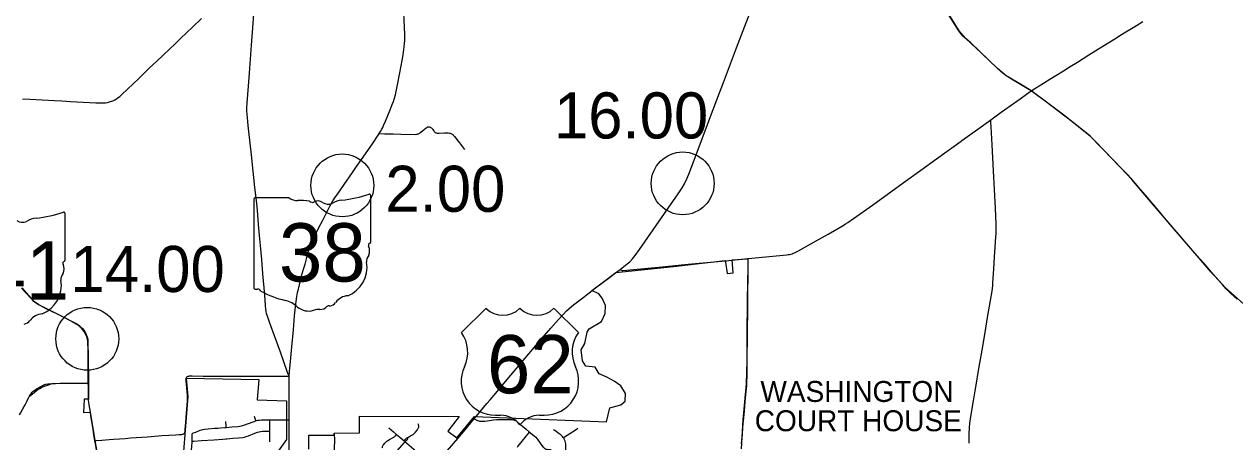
# Model space of a CAD drawing. Extents: x 1597222 to 1925846, y 496284 to 911751.
# Drawn here: x 1698562 to 1727439, y 566794 to 576766 of the extents above; entities that cross this region are included whole.
import ezdxf

# ---------------------------------------------------------------- set-up
doc = ezdxf.new("R2010")
doc.units = 0
for name, color, linetype in [('Default', 7, 'Continuous'), ('GM_X_City_Street', 7, 'Continuous'), ('GM_X_Corporation', 7, 'Continuous'), ('GM_X_Corporation_Text', 7, 'Continuous'), ('GM_X_County_Road', 7, 'Continuous'), ('GM_X_State_Route', 7, 'Continuous'), ('GM_X_State_Shield', 7, 'Continuous'), ('GM_X_Township', 7, 'Continuous'), ('GM_X_Township_Road', 7, 'Continuous'), ('GM_X_US_Route', 7, 'Continuous'), ('GM_X_US_Shield', 7, 'Continuous')]:
    doc.layers.add(name, color=color, linetype=linetype)

msp = doc.modelspace()

# ---------------------------------------------------------------- linework, layer by layer
at = {"layer": 'Default'}
for centre in [(1706150, 572917), (1706150, 572917), (1714269, 572965), (1714269, 572965), (1700066, 569254), (1700066, 569254)]:
    msp.add_circle(centre, 750, dxfattribs=at)
at = {"layer": 'GM_X_City_Street'}
for points in [[(1698690, 567886), (1698759, 567939), (1698809, 567983), (1698848, 568013), (1698889, 568042), (1698931, 568068), (1698975, 568091), (1699021, 568111), (1699067, 568129), (1699115, 568144), (1699227, 568183)], [(1698690, 567886), (1698719, 567934), (1698734, 567956), (1698754, 567978), (1698779, 568000), (1698817, 568031), (1698858, 568059), (1698899, 568086), (1698943, 568110), (1698987, 568132), (1699033, 568151), (1699079, 568167), (1699126, 568176), (1699175, 568182), (1699227, 568183)], [(1699227, 568183), (1699259, 568186), (1699309, 568187), (1699422, 568191), (1699683, 568193), (1699976, 568196), (1700091, 568197)], [(1698451, 567435), (1698474, 567479), (1698532, 567579), (1698587, 567680), (1698623, 567754), (1698665, 567843), (1698681, 567872), (1698690, 567886)], [(1703380, 567139), (1703378, 567172), (1703371, 567280)], [(1703380, 567139), (1703517, 567149), (1703658, 567161), (1703703, 567168), (1703745, 567177), (1703798, 567194), (1704023, 567274), (1704087, 567295)], [(1704087, 567295), (1704085, 567301), (1704056, 567401)], [(1704087, 567295), (1704101, 567300), (1704133, 567308), (1704175, 567314), (1704220, 567317), (1704352, 567318), (1704423, 567318)], [(1704422, 567046), (1704422, 567091), (1704423, 567274), (1704423, 567318)], [(1704423, 567318), (1704594, 567318), (1704830, 567315), (1704879, 567315)], [(1707714, 566893), (1707736, 566911), (1707756, 566923), (1707779, 566936), (1707808, 566951), (1707824, 566961), (1707837, 566969), (1707848, 566979), (1707860, 566990), (1707893, 567025), (1707933, 567076), (1707953, 567102), (1707961, 567116), (1707967, 567130), (1707972, 567146), (1707975, 567162), (1707975, 567171), (1707974, 567178), (1707971, 567194), (1707966, 567209), (1707960, 567224)], [(1709297, 567343), (1709345, 567320), (1709375, 567306), (1709405, 567295), (1709420, 567290), (1709436, 567287), (1709468, 567284), (1709500, 567285), (1709549, 567289), (1709662, 567305), (1709760, 567319), (1709825, 567326), (1709891, 567329), (1710072, 567329), (1710170, 567329), (1710204, 567326), (1710220, 567323), (1710236, 567319), (1710252, 567314), (1710268, 567307), (1710283, 567300), (1710297, 567291), (1710324, 567272), (1710538, 567093), (1710617, 567027)], [(1702566, 566807), (1702567, 566835), (1702566, 566884), (1702565, 566933), (1702567, 566957), (1702569, 566977), (1702570, 566986), (1702572, 566992)], [(1702566, 566807), (1702607, 566810), (1702788, 566823), (1703085, 566844), (1703299, 566861), (1703371, 566867), (1703393, 566869), (1703537, 566880), (1703675, 566890), (1703776, 566900), (1703815, 566907), (1703860, 566918), (1703912, 566936), (1704064, 566998), (1704128, 567024), (1704166, 567036), (1704201, 567043), (1704244, 567046), (1704296, 567047), (1704385, 567046), (1704422, 567046)], [(1702572, 566992), (1702576, 566996), (1702582, 567000), (1702601, 567008), (1702654, 567027), (1702760, 567069), (1702791, 567080), (1702823, 567088), (1702871, 567096), (1702952, 567104), (1703099, 567116), (1703183, 567123), (1703240, 567128), (1703344, 567136), (1703380, 567139)], [(1704423, 566793), (1704422, 566915), (1704422, 567046)], [(1705965, 566411), (1705964, 566428), (1705966, 566591), (1705969, 566870), (1705966, 566950), (1705963, 566962), (1705960, 566970), (1705957, 566976), (1705952, 566986)], [(1707104, 566650), (1707105, 566666), (1707108, 566682), (1707114, 566697), (1707122, 566711), (1707132, 566724), (1707163, 566761), (1707184, 566785), (1707208, 566807), (1707235, 566825), (1707276, 566850), (1707348, 566887), (1707376, 566904), (1707389, 566913), (1707401, 566922), (1707414, 566933), (1707428, 566947), (1707446, 566968)], [(1707261, 567124), (1707374, 567029), (1707446, 566968)], [(1707446, 566968), (1707523, 566901), (1707623, 566816)], [(1707623, 566816), (1707645, 566842), (1707663, 566863), (1707673, 566875), (1707679, 566882), (1707685, 566887), (1707692, 566890), (1707698, 566891), (1707706, 566893), (1707714, 566893)], [(1707647, 566795), (1707668, 566818), (1707678, 566828), (1707686, 566837), (1707692, 566843), (1707701, 566852), (1707712, 566866), (1707715, 566873), (1707716, 566879), (1707716, 566886), (1707714, 566893)], [(1710325, 566670), (1710333, 566680), (1710513, 566893), (1710617, 567027)], [(1710617, 567027), (1710727, 566935), (1710763, 566901), (1710786, 566877), (1710816, 566838), (1710913, 566705), (1710942, 566666), (1710953, 566655), (1710965, 566644), (1710978, 566635), (1710992, 566628), (1711007, 566622), (1711022, 566618), (1711038, 566615), (1711128, 566609)], [(1711425, 566891), (1711421, 566898), (1711401, 566924), (1711378, 566947), (1711353, 566969), (1711326, 566988), (1711286, 567016), (1711217, 567062), (1711191, 567082)], [(1711425, 566891), (1711452, 566910), (1711642, 567035), (1711750, 567107), (1711764, 567116)], [(1711478, 566594), (1711479, 566614), (1711483, 566696), (1711482, 566729), (1711480, 566745), (1711473, 566777), (1711464, 566809), (1711452, 566840), (1711438, 566870), (1711425, 566891)], [(1702543, 566532), (1702557, 566672), (1702566, 566802), (1702566, 566807)], [(1706725, 565792), (1706776, 565835), (1706889, 565930), (1706950, 565984), (1706985, 566020), (1707040, 566081), (1707219, 566295), (1707409, 566520), (1707622, 566770), (1707647, 566795)], [(1707623, 566816), (1707647, 566795)], [(1707647, 566795), (1707685, 566762), (1707912, 566574), (1707961, 566531), (1707985, 566507), (1708007, 566482), (1708027, 566456), (1708078, 566373), (1708098, 566347), (1708102, 566343)]]:
    msp.add_lwpolyline(points, dxfattribs=at)
at = {"layer": 'GM_X_Corporation'}
for points in [[(1705355, 566620), (1705355, 566950), (1705487, 566950), (1705934, 566950), (1705959, 566950), (1705959, 567000), (1706558, 567010), (1706558, 567408), (1708934, 567398), (1708666, 567046), (1708879, 566889), (1709303, 567401), (1712454, 567272), (1712535, 567608), (1712790, 567676), (1712894, 567766), (1712902, 567946), (1712796, 568133), (1712633, 568245), (1712458, 568338), (1712277, 568417), (1712180, 568574), (1711956, 568601), (1711877, 568731), (1711845, 568993), (1711937, 569143), (1711990, 569409), (1712037, 569494), (1712334, 569669), (1712422, 569854), (1712428, 570049), (1712352, 570224), (1712272, 570329), (1712103, 570404), (1712350, 570593), (1712672, 570840), (1714050, 570984), (1715285, 571126), (1715291, 571086), (1715327, 570812), (1715474, 570829), (1715450, 571138), (1715821, 571166), (1715821, 571110), (1715815, 569998), (1715797, 568730), (1715787, 568186), (1715778, 568091), (1715706, 567322), (1715667, 566626)], [(1698502, 570468), (1698717, 570227), (1698810, 570138), (1698903, 570071), (1699509, 569770), (1699703, 569669), (1699856, 569583), (1699906, 569543), (1699954, 569500), (1700008, 569426), (1700033, 569383), (1700078, 569248), (1700083, 569175), (1700086, 568816), (1700098, 568180), (1700094, 567887), (1700097, 567813), (1699989, 567809), (1699976, 567494), (1700138, 567499), (1700250, 566822), (1700318, 566418)], [(1702357, 566364), (1702402, 566969), (1702470, 567879), (1702469, 567879), (1702432, 568315), (1704158, 568278), (1704122, 567798), (1704821, 567771), (1704817, 566848), (1704579, 566512)]]:
    msp.add_lwpolyline(points, dxfattribs=at)
at = {"layer": 'GM_X_County_Road'}
for points in [[(1722580, 575173), (1722488, 575232), (1722291, 575349), (1722149, 575432), (1722023, 575509), (1721983, 575536), (1721943, 575566), (1721866, 575628), (1721758, 575729), (1721604, 575876), (1721402, 576068), (1721259, 576203), (1721034, 576419), (1720954, 576501), (1720926, 576533), (1720900, 576564), (1720852, 576631), (1720694, 576880), (1720522, 577159), (1720383, 577382), (1720317, 577496), (1720233, 577655), (1720167, 577787), (1720153, 577815)], [(1704423, 569626), (1704379, 569750), (1704358, 569813), (1704345, 569860), (1704334, 569909), (1704327, 569958), (1704320, 570040), (1704298, 570301), (1704255, 570808), (1704226, 571151), (1704198, 571478), (1704177, 571723), (1704154, 571984), (1704123, 572327), (1704100, 572556), (1704065, 572866), (1703981, 573648), (1703951, 573926), (1703920, 574203), (1703904, 574349), (1703885, 574529), (1703878, 574627), (1703875, 574693), (1703875, 574759), (1703881, 574890), (1703910, 575283), (1703935, 575593), (1703985, 576264), (1704009, 576575), (1704049, 577115)], [(1698519, 574983), (1698697, 574974), (1699287, 574943), (1699456, 574936), (1699663, 574924), (1700270, 574892), (1700401, 574887), (1700450, 574888), (1700500, 574892), (1700549, 574899), (1700597, 574911), (1700644, 574925), (1700675, 574937), (1700720, 574959), (1700763, 574983), (1700803, 575012), (1700842, 575043), (1700891, 575087), (1701294, 575472), (1701554, 575721), (1701721, 575879), (1701875, 576027), (1702030, 576173), (1702160, 576298), (1702290, 576423), (1702443, 576571), (1702574, 576694), (1702787, 576899)], [(1722580, 575173), (1722611, 575193), (1722667, 575230), (1722876, 575360), (1723029, 575455), (1723168, 575541), (1723351, 575656), (1723516, 575757), (1723684, 575862), (1723960, 576035), (1724128, 576139), (1724393, 576302), (1724616, 576440), (1724700, 576494), (1724839, 576580), (1724932, 576638), (1725091, 576738), (1725244, 576833)], [(1721618, 574483), (1721682, 574529), (1721868, 574664), (1722162, 574874), (1722322, 574987), (1722469, 575093), (1722580, 575173)], [(1727499, 570198), (1727353, 570330), (1727236, 570445), (1727137, 570555), (1726920, 570801), (1726707, 571050), (1726599, 571174), (1726437, 571358), (1725944, 571930), (1725806, 572092), (1725617, 572319), (1725309, 572681), (1725192, 572819), (1725066, 572969), (1724980, 573068), (1724857, 573200), (1724685, 573376), (1724308, 573764), (1724114, 573964), (1723999, 574081), (1723913, 574156), (1723759, 574278), (1723552, 574440), (1723360, 574593), (1723140, 574764), (1722915, 574929), (1722743, 575054), (1722580, 575173)], [(1720932, 573989), (1721309, 574262), (1721618, 574483)], [(1721102, 566763), (1721105, 566977), (1721110, 567124), (1721121, 567238), (1721144, 567400), (1721205, 567773), (1721246, 568015), (1721275, 568194), (1721317, 568453), (1721340, 568582), (1721425, 569067), (1721498, 569504), (1721552, 569811), (1721613, 570167), (1721648, 570395), (1721664, 570525), (1721670, 570589), (1721691, 570918), (1721710, 571213), (1721726, 571442), (1721742, 571688), (1721747, 571761), (1721750, 571847), (1721747, 571984), (1721728, 572377), (1721706, 572820), (1721683, 573263), (1721651, 573886), (1721630, 574312), (1721622, 574427), (1721618, 574483)], [(1707027, 574153), (1707037, 574153), (1707164, 574150), (1707271, 574148), (1707363, 574145), (1707542, 574141), (1707887, 574136), (1707920, 574138), (1707936, 574141), (1707952, 574146), (1707955, 574147)], [(1707955, 574147), (1707967, 574152), (1707982, 574159), (1707996, 574168), (1708023, 574187), (1708074, 574227), (1708149, 574291), (1708163, 574300), (1708178, 574307), (1708193, 574312), (1708210, 574314), (1708226, 574313), (1708242, 574310), (1708257, 574304), (1708271, 574295), (1708284, 574285), (1708295, 574273), (1708305, 574260), (1708331, 574218), (1708341, 574204), (1708352, 574192), (1708364, 574182), (1708379, 574175), (1708394, 574170), (1708410, 574166), (1708427, 574165), (1708460, 574165), (1708591, 574172), (1708640, 574173), (1708673, 574171), (1708706, 574166), (1708722, 574162), (1708737, 574157), (1708752, 574150), (1708767, 574142), (1708780, 574133), (1708792, 574122), (1708804, 574110), (1708826, 574086), (1708948, 573931), (1709017, 573839), (1709067, 573774)], [(1715834, 571172), (1716752, 571259), (1716789, 571264), (1716820, 571270), (1716847, 571275), (1716880, 571285), (1716908, 571295), (1716940, 571309), (1717013, 571346), (1717197, 571451), (1717455, 571594), (1717741, 571756), (1718096, 571963), (1718152, 571997), (1718208, 572031), (1718342, 572124), (1718796, 572447), (1719527, 572975), (1719953, 573283), (1720326, 573552), (1720578, 573734), (1720910, 573973), (1720932, 573989)], [(1712778, 570910), (1712808, 570892), (1712819, 570886), (1712827, 570883), (1712833, 570881), (1712839, 570881), (1713095, 570906), (1713700, 570962), (1714400, 571033), (1715022, 571093), (1715289, 571118)], [(1715289, 571118), (1715451, 571134)], [(1715451, 571134), (1715822, 571170), (1715834, 571172)], [(1715675, 566757), (1715692, 566970), (1715706, 567133), (1715720, 567297), (1715742, 567526), (1715763, 567755), (1715787, 568000), (1715796, 568132), (1715801, 568246), (1715805, 568344), (1715804, 568705), (1715805, 568951), (1715806, 569181), (1715807, 569395), (1715810, 569624), (1715815, 569887), (1715817, 570117), (1715825, 570659), (1715828, 570889), (1715831, 571069), (1715833, 571135), (1715834, 571172)], [(1704531, 569328), (1704445, 569565), (1704423, 569626)], [(1704883, 568361), (1704845, 568450), (1704756, 568701), (1704674, 568932), (1704531, 569328)]]:
    msp.add_lwpolyline(points, dxfattribs=at)
at = {"layer": 'GM_X_State_Route'}
for points in [[(1705179, 570752), (1705180, 570755), (1705227, 570913), (1705263, 571039), (1705304, 571198), (1705338, 571324), (1705362, 571403), (1705389, 571480), (1705420, 571556), (1705453, 571630), (1705510, 571748), (1705592, 571909), (1705674, 572070), (1705852, 572421), (1705891, 572494), (1705924, 572550), (1705968, 572619), (1706071, 572767), (1706194, 572941), (1706391, 573224), (1706475, 573346), (1706605, 573535), (1706866, 573913), (1707004, 574117), (1707027, 574153), (1707057, 574200), (1707090, 574257), (1707113, 574301), (1707134, 574346), (1707178, 574452), (1707292, 574724), (1707342, 574846), (1707370, 574923), (1707395, 575001), (1707416, 575081), (1707435, 575161), (1707473, 575354), (1707555, 575773), (1707580, 575902), (1707601, 576032), (1707627, 576227), (1707636, 576308), (1707641, 576374), (1707643, 576440), (1707642, 576522), (1707635, 576686), (1707611, 577227)], [(1704985, 569470), (1705013, 569804), (1705034, 570017), (1705049, 570147), (1705066, 570260), (1705083, 570357), (1705101, 570437), (1705151, 570644), (1705179, 570752)], [(1700093, 568065), (1700093, 568112), (1700091, 568197), (1700090, 568306), (1700090, 568600), (1700087, 568879), (1700085, 569042), (1700082, 569124), (1700076, 569189), (1700069, 569237), (1700061, 569268), (1700052, 569300), (1700035, 569345), (1700014, 569389), (1699990, 569431), (1699962, 569471), (1699931, 569509), (1699908, 569532), (1699885, 569554), (1699846, 569583), (1699805, 569610), (1699748, 569642), (1699646, 569694), (1699500, 569767), (1699354, 569841), (1699089, 569971), (1698959, 570040), (1698902, 570072), (1698860, 570098), (1698833, 570117), (1698794, 570148), (1698758, 570182), (1698712, 570229), (1698602, 570350), (1698500, 570463)], [(1704893, 568482), (1704898, 568546), (1704914, 568709), (1704954, 569151), (1704984, 569461), (1704985, 569470)], [(1704879, 567457), (1704879, 567719), (1704879, 567774), (1704881, 568024), (1704882, 568143), (1704883, 568361), (1704893, 568482)], [(1700094, 567812), (1700092, 567914), (1700093, 568065)], [(1700140, 567499), (1700110, 567673), (1700101, 567741), (1700097, 567791), (1700094, 567812)], [(1700345, 566242), (1700331, 566314), (1700267, 566703), (1700248, 566819), (1700233, 566913), (1700197, 567140), (1700153, 567415), (1700140, 567499)], [(1704879, 567236), (1704879, 567315), (1704879, 567326), (1704879, 567457)], [(1704883, 566054), (1704881, 566541), (1704881, 566579), (1704881, 566619), (1704881, 566666), (1704881, 566706), (1704881, 566748), (1704880, 566799), (1704880, 566819), (1704880, 566849), (1704880, 566984), (1704879, 567236)]]:
    msp.add_lwpolyline(points, dxfattribs=at)
at = {"layer": 'GM_X_State_Shield'}
for p, q in [((1706827, 571569), (1706827, 572674)), ((1704042, 572585), (1704042, 570472)), ((1704885, 572622), (1704070, 572622)), ((1699536, 571138), (1699536, 572243)), ((1706826, 571569), (1706827, 571569)), ((1699536, 571138), (1699536, 571138))]:
    msp.add_line(p, q, dxfattribs=at)
for centre, radius, start, end in [((1705835, 575503), 2953, 275.8445, 288.9065), ((1706796, 572679), 31, 351.8621, 97.738), ((1704074, 572590), 32.3, 98.1301, 188.1301), ((1705079, 572867), 313, 231.6195, 271.1119), ((1705183, 571435), 1123, 80.4867, 94.9883), ((1705438, 572601), 90.3, 219.7921, 297.1024), ((1705571, 572357), 188, 54.4667, 119.1411), ((1705813, 572692), 226, 233.8562, 294.8282), ((1706211, 571976), 594, 97.3462, 120.7689), ((1698522, 572260), 226, 233.8562, 294.8282), ((1698921, 571545), 594, 97.3462, 120.7689), ((1698544, 575072), 2953, 275.8445, 288.9065), ((1699505, 572248), 31, 351.8621, 97.738), ((1706819, 571488), 48, 107.944, 210.337), ((1706794, 571564), 33.2, 289.6038, 7.7341), ((1706938, 571106), 210, 136.8065, 186.9296), ((1706514, 571348), 288, 340.033, 23.6496), ((1699529, 571056), 48, 107.944, 210.337), ((1699224, 570917), 288, 340.033, 23.6496), ((1699503, 571133), 33.2, 289.6038, 7.7341), ((1706000, 570965), 739, 292.3089, 8.9858), ((1698709, 570534), 739, 292.3089, 8.9858), ((1699647, 570675), 210, 136.8065, 186.9296), ((1704075, 570468), 32.5, 171.9584, 258.3066), ((1704079, 570684), 248, 267.339, 280.6039), ((1704130, 570350), 89.5, 29.7484, 93.2717), ((1705261, 572249), 2132, 240.4129, 257.1985), ((1704625, 569523), 667, 47.1842, 75.836), ((1705799, 570267), 239, 282.8732, 323.2771), ((1706312, 569879), 404, 94.4031, 142.5768), ((1699021, 569448), 404, 94.4031, 142.5768), ((1705347, 570340), 423, 230.7004, 286.2918), ((1705591, 569609), 348, 85.6951, 111.2099), ((1705622, 570182), 226, 268.777, 315.5493), ((1705826, 569977), 63.5, 65.7517, 132.6484), ((1698508, 569836), 239, 282.8732, 323.2771)]:
    msp.add_arc(centre, radius, start, end, dxfattribs=at)
at = {"layer": 'GM_X_Township'}
msp.add_lwpolyline([(1727867, 569889), (1727212, 570476), (1726878, 570847), (1725432, 572534), (1724986, 573061), (1724579, 573488), (1723975, 574112), (1723550, 574442), (1722918, 574928), (1722572, 575179), (1722311, 575341), (1721987, 575534), (1721782, 575706), (1721140, 576318), (1720955, 576480), (1720855, 576610), (1720323, 577460)], dxfattribs=at)
at = {"layer": 'GM_X_Township_Road'}
for points in [[(1702421, 568270), (1702420, 568282), (1702421, 568299), (1702424, 568315), (1702430, 568331), (1702441, 568345), (1702454, 568355), (1702470, 568362), (1702487, 568365), (1702503, 568367), (1702570, 568366), (1702832, 568365), (1703257, 568364), (1703682, 568364), (1704026, 568362), (1704167, 568362)], [(1704167, 568362), (1704395, 568361), (1704560, 568361), (1704824, 568361), (1704883, 568361)], [(1702374, 566989), (1702382, 566996), (1702386, 567001), (1702390, 567007), (1702394, 567013), (1702396, 567019), (1702398, 567026), (1702401, 567042), (1702405, 567091), (1702415, 567254), (1702425, 567385), (1702446, 567662), (1702454, 567792), (1702456, 567858), (1702455, 567906), (1702450, 567988), (1702440, 568085), (1702423, 568248), (1702421, 568270)], [(1700248, 566819), (1700279, 566822), (1700410, 566830), (1700590, 566846), (1700688, 566854), (1700836, 566864), (1700967, 566875), (1701097, 566886), (1701506, 566915), (1701843, 566941)], [(1701843, 566941), (1702011, 566953), (1702175, 566964), (1702256, 566968), (1702321, 566972), (1702337, 566975), (1702353, 566977), (1702365, 566982), (1702374, 566989)]]:
    msp.add_lwpolyline(points, dxfattribs=at)
at = {"layer": 'GM_X_US_Route'}
for points in [[(1712778, 570910), (1712823, 570945), (1712945, 571040), (1713005, 571095), (1713072, 571166), (1713135, 571242), (1713241, 571387), (1713763, 572143), (1713997, 572479), (1714147, 572694), (1714256, 572858), (1714313, 572958), (1714370, 573075), (1714415, 573181), (1714542, 573518), (1714936, 574562), (1715150, 575129), (1715242, 575375), (1715554, 576203), (1715869, 577031)], [(1712225, 570494), (1712494, 570697), (1712634, 570802)], [(1712634, 570802), (1712778, 570910)], [(1709346, 567401), (1709599, 567706), (1709673, 567794), (1709810, 567957), (1710042, 568234), (1710422, 568685), (1710686, 568999), (1710855, 569199), (1711124, 569509), (1711310, 569716), (1711421, 569837), (1711501, 569919), (1711560, 569976), (1711622, 570030), (1711698, 570092), (1711853, 570212), (1712225, 570494)], [(1708904, 566873), (1709037, 567031), (1709216, 567245), (1709287, 567331), (1709297, 567343), (1709329, 567381)], [(1709329, 567381), (1709346, 567401)], [(1707911, 565695), (1707917, 565702), (1708108, 565927), (1708255, 566103), (1708306, 566164), (1708582, 566492), (1708654, 566578), (1708904, 566873)]]:
    msp.add_lwpolyline(points, dxfattribs=at)
at = {"layer": 'GM_X_US_Shield'}
for p, q in [((1709575, 569981), (1708995, 569401)), ((1711780, 569401), (1711200, 569981)), ((1709807, 567429), (1709923, 567429)), ((1710851, 567429), (1710967, 567429))]:
    msp.add_line(p, q, dxfattribs=at)
for centre, radius, start, end in [((1709981, 570396), 580, 225.573, 314.427), ((1710793, 570396), 580, 225.573, 314.427), ((1708330, 568935), 812, 334.5471, 35.0009), ((1712445, 568935), 812, 144.9991, 205.4529), ((1709798, 568241), 812, 154.8319, 270.6383), ((1710977, 568241), 812, 269.3617, 25.1681), ((1709923, 566849), 580, 36.8699, 90), ((1710851, 566849), 580, 90, 143.1301)]:
    msp.add_arc(centre, radius, start, end, dxfattribs=at)

# ---------------------------------------------------------------- texts
at = {"layer": 'Default'}
for s, p in [('16.00', (1711198, 574037)), ('16.00', (1711198, 574037)), ('2.00', (1707176, 572286)), ('2.00', (1707176, 572286)), ('14.00', (1699665, 570372)), ('14.00', (1699665, 570372))]:
    msp.add_text(s, height=1100, dxfattribs=at).set_placement(p)
at = {"layer": 'GM_X_Corporation_Text'}
for s, p in [('WASHINGTON', (1716123, 567746)), ('COURT HOUSE', (1715988, 567047))]:
    msp.add_text(s, height=500, rotation=0, dxfattribs=at).set_placement(p)
at = {"layer": 'GM_X_State_Shield'}
for s, p in [('38', (1704639, 570621)), ('41', (1697566, 570190))]:
    msp.add_text(s, height=1392.2, dxfattribs=at).set_placement(p)
at = {"layer": 'GM_X_US_Shield'}
msp.add_text('62', height=1392.2, dxfattribs=at).set_placement((1709599, 567951))

doc.saveas('drawing.dxf')
